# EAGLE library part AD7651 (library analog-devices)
16-Bit 100 kSPS PulSARTM Unipolar ADC with Reference Source: COMPLIANT TO JEDEC STANDARDS MO-220-VKKD-2
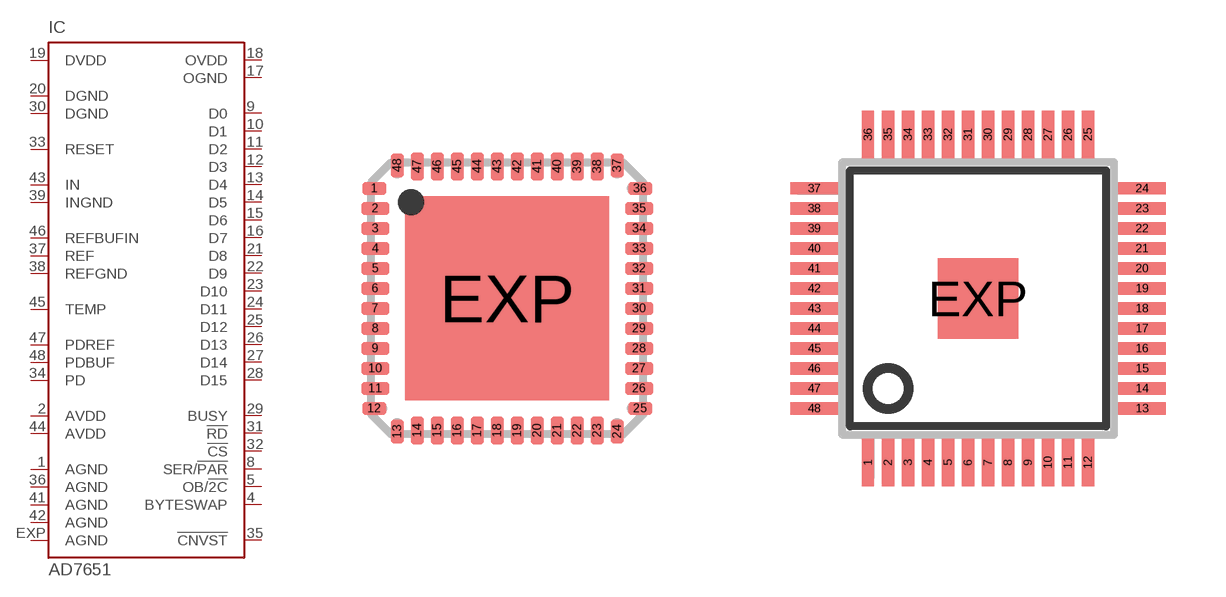
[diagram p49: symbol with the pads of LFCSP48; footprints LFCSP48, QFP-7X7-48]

Designator prefix IC

## AD7651ACP (OC_FARNELL: unknown; OC_NEWARK: unknown)  [LFCSP48]
1  AGND  in
2  AVDD  in
4  BYTESWAP  in
5  OB/!2C  in
8  SER/!PAR  in
9  D0  in
10  D1  in
11  D2  in
12  D3  in
13  D4  in
14  D5  in
15  D6  in
16  D7  in
17  OGND  in
18  OVDD  in
19  DVDD  in
20  DGND  in
21  D8  in
22  D9  in
23  D10  in
24  D11  in
25  D12  in
26  D13  in
27  D14  in
28  D15  in
29  BUSY  in
30  DGND  in
31  !RD  in
32  !CS  in
33  RESET  in
34  PD  in
35  !CNVST  in
36  AGND  in
37  REF  in
38  REFGND  in
39  INGND  in
41  AGND  in
42  AGND  in
43  IN  in
44  AVDD  in
45  TEMP  in
46  REFBUFIN  in
47  PDREF  in
48  PDBUF  in
EXP  AGND  in

## AD7651AST (MPN: AD7651ASTZ; OC_FARNELL: 1581929; OC_NEWARK: 15P0825)  [QFP-7X7-48]
Pads as for LFCSP48

## Footprint LFCSP48 (pad centres in mm)
Lead Frame Chip Scale Package LFCSP CP-48 COMPLIANT TO JEDEC STANDARDS MO-220-VKKD-2 Source: http://www.analog.com/UploadedFiles/Data_Sheets/39780344872292AD7651_0.pdf
smd 0.6 x 0.32: 1 -3.325,2.75; 12 -3.325,-2.75; 25 3.325,-2.75; 36 3.325,2.75
smd 0.7 x 0.32: 2 -3.3,2.25; 3 -3.3,1.75; 4 -3.3,1.25; 5 -3.3,0.75; 6 -3.3,0.25; 7 -3.3,-0.25; 8 -3.3,-0.75; 9 -3.3,-1.25; 10 -3.3,-1.75; 11 -3.3,-2.25; 26 3.3,-2.25; 27 3.3,-1.75; 28 3.3,-1.25; 29 3.3,-0.75; 30 3.3,-0.25; 31 3.3,0.25; 32 3.3,0.75; 33 3.3,1.25; 34 3.3,1.75; 35 3.3,2.25
smd 0.32 x 0.6: 13 -2.75,-3.325; 24 2.75,-3.325; 37 2.75,3.325; 48 -2.75,3.325
smd 0.32 x 0.7: 14 -2.25,-3.3; 15 -1.75,-3.3; 16 -1.25,-3.3; 17 -0.75,-3.3; 18 -0.25,-3.3; 19 0.25,-3.3; 20 0.75,-3.3; 21 1.25,-3.3; 22 1.75,-3.3; 23 2.25,-3.3; 38 2.25,3.3; 39 1.75,3.3; 40 1.25,3.3; 41 0.75,3.3; 42 0.25,3.3; 43 -0.25,3.3; 44 -0.75,3.3; 45 -1.25,3.3; 46 -1.75,3.3; 47 -2.25,3.3
smd 5.1 x 5.1: EXP 0,0

## Footprint QFP-7X7-48 (pad centres in mm)
TQFP48 7x7 Thin Plastic Quad Flat Package, Exposed Pad, TQFP/EP Source: www.analog.com/UploadedFiles/Data_Sheets/33830397585263AD9859_0.pdf
smd 0.3 x 1.2: 1 -2.75,-4.1; 2 -2.25,-4.1; 3 -1.75,-4.1; 4 -1.25,-4.1; 5 -0.75,-4.1; 6 -0.25,-4.1; 7 0.25,-4.1; 8 0.75,-4.1; 9 1.25,-4.1; 10 1.75,-4.1; 11 2.25,-4.1; 12 2.75,-4.1; 25 2.75,4.1; 26 2.25,4.1; 27 1.75,4.1; 28 1.25,4.1; 29 0.75,4.1; 30 0.25,4.1; 31 -0.25,4.1; 32 -0.75,4.1; 33 -1.25,4.1; 34 -1.75,4.1; 35 -2.25,4.1; 36 -2.75,4.1
smd 1.2 x 0.3: 13 4.1,-2.75; 14 4.1,-2.25; 15 4.1,-1.75; 16 4.1,-1.25; 17 4.1,-0.75; 18 4.1,-0.25; 19 4.1,0.25; 20 4.1,0.75; 21 4.1,1.25; 22 4.1,1.75; 23 4.1,2.25; 24 4.1,2.75; 37 -4.1,2.75; 38 -4.1,2.25; 39 -4.1,1.75; 40 -4.1,1.25; 41 -4.1,0.75; 42 -4.1,0.25; 43 -4.1,-0.25; 44 -4.1,-0.75; 45 -4.1,-1.25; 46 -4.1,-1.75; 47 -4.1,-2.25; 48 -4.1,-2.75
smd 2 x 2: EXP 0,0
